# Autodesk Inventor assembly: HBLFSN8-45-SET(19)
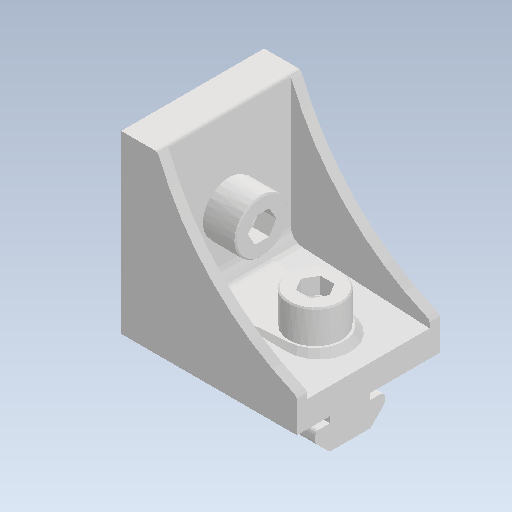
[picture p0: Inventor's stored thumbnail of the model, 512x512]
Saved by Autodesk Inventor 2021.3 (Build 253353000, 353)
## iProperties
Created: 2022-02
Part Number: HBLFSN8-45-SET(19)
Document SubType Name: Assembly
Designer: kengo
Author: kengo
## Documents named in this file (4)
- C:\Users\kengo\Documents\S2S_frame\SDC345\frame_misumi_ver12\HBLFSN8-45-SET(19).iam
- C:\Users\kengo\Documents\S2S_frame\SDC345\frame_misumi_ver12\HBLFSN8-45.ipt
- C:\Users\kengo\Documents\S2S_frame\SDC345\frame_misumi_ver12\HNTT8-8.ipt
- C:\Users\kengo\Documents\S2S_frame\SDC345\frame_misumi_ver12\CBM8-20.ipt
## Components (5 placed, 3 different names)
1. HBLFSN8-45
2. HNTT8-8
3. CBM8-20
4. HNTT8-8:1
5. CBM8-20:1
